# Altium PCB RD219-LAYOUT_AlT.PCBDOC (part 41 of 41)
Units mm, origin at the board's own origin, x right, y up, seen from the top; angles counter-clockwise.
Board outline 209.75 x 159.97 mm, 2 copper layers (TOP, BOTTOM), stack 0 mm thick; 398 components, 199 nets, 1469 pads, 0 vias.
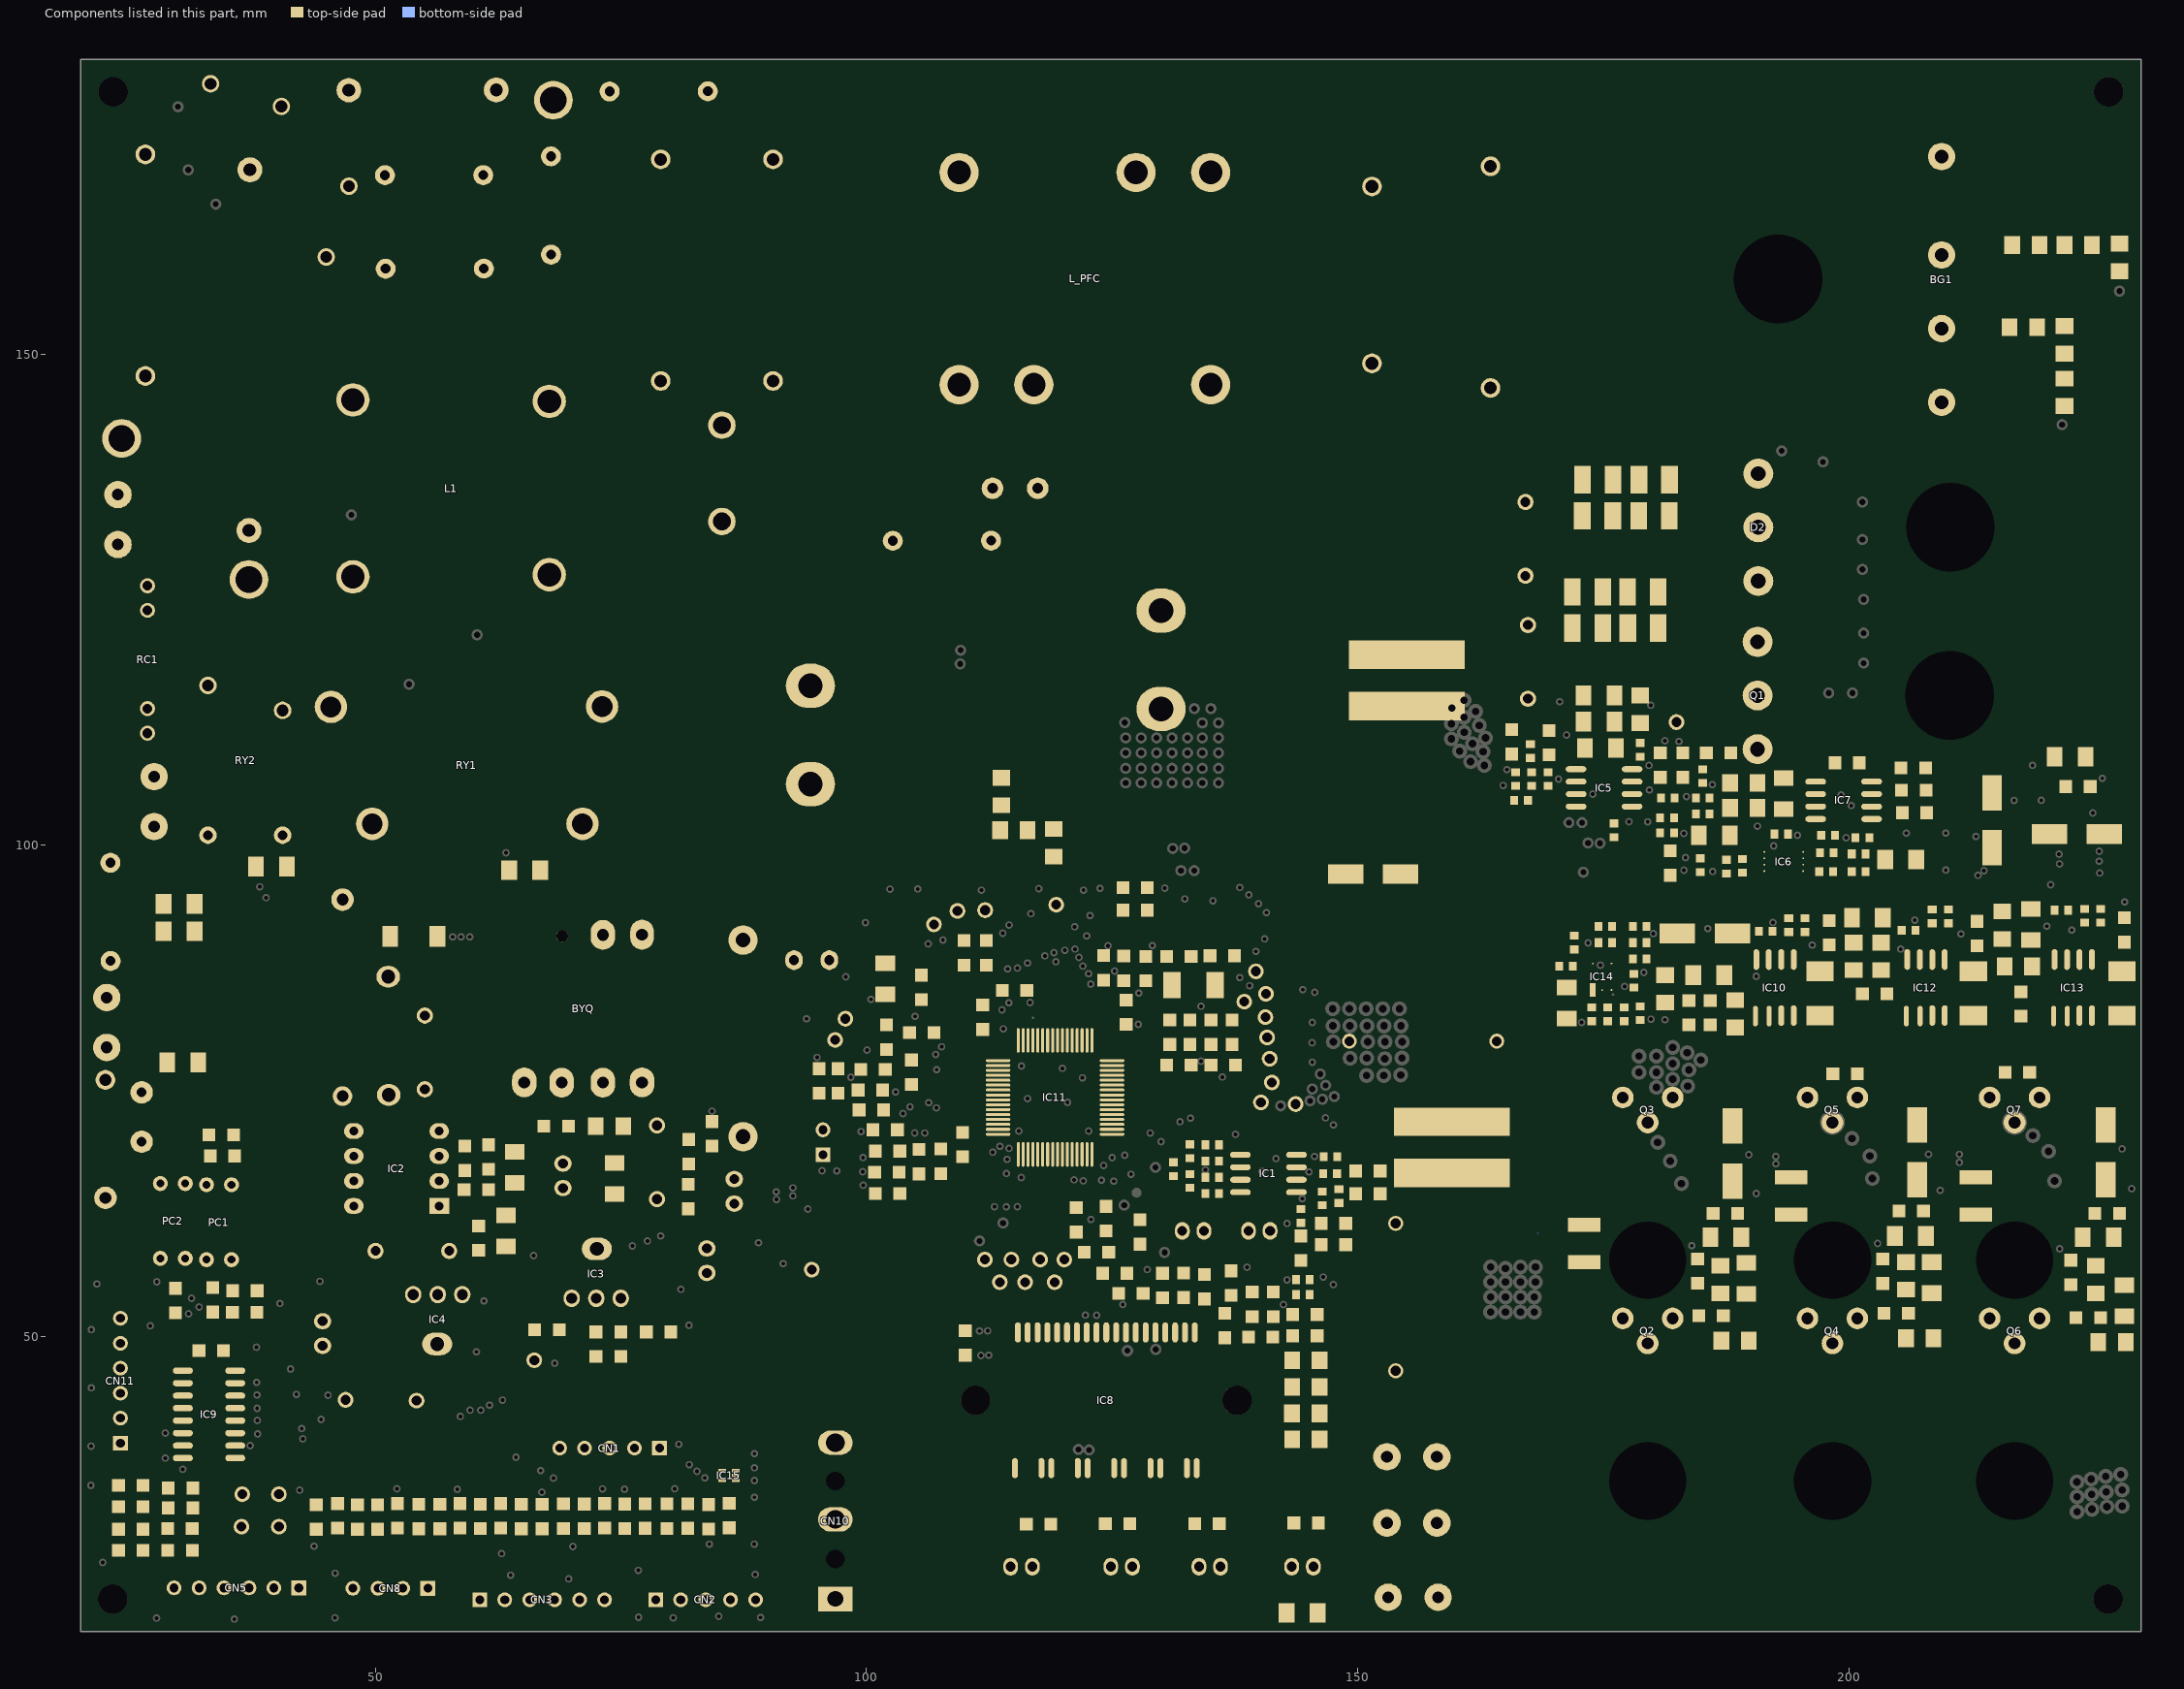
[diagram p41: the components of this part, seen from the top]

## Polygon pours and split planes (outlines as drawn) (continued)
no net on Bottom Solder "BOTTOMSOLDER377" (solid, pour order 0): 187.178,122.13 187.178,123.378 189.372,123.378 189.372,122.13
no net on Bottom Solder "BOTTOMSOLDER376" (solid, pour order 0): 184.638,122.13 184.638,123.378 186.832,123.378 186.832,122.13
no net on Bottom Solder "BOTTOMSOLDER375" (solid, pour order 0): 153.033,116.838 151.636,118.235 155.192,121.791 156.589,120.394
no net on Bottom Solder "BOTTOMSOLDER374" (solid, pour order 0): 160.843,125.791 160.843,128.331 164.297,128.331 164.297,125.791
no net on Bottom Solder "BOTTOMSOLDER373" (solid, pour order 0): 150.937,84.77 150.937,87.987 153.477,87.987 153.477,84.77
no net on Bottom Solder "BOTTOMSOLDER372" (solid, pour order 0): 147.339,85.024 147.339,90.612 149.879,90.612 149.879,85.024
no net on Bottom Solder "BOTTOMSOLDER371" (solid, pour order 0): 145.913,90.828 142.357,94.384 143.754,95.781 147.31,92.225
no net on Bottom Solder "BOTTOMSOLDER370" (solid, pour order 0): 148.707,92.479 145.151,96.035 146.548,97.432 150.104,93.876
no net on Bottom Solder "BOTTOMSOLDER369" (solid, pour order 0): 142.191,94.731 138.635,98.287 140.032,99.684 143.588,96.128
no net on Bottom Solder "BOTTOMSOLDER368" (solid, pour order 0): 144.227,96.725 140.671,100.281 142.068,101.678 145.624,98.122
no net on Bottom Solder "BOTTOMSOLDER367" (solid, pour order 0): 137.747,99.33 134.191,102.886 135.588,104.283 139.144,100.727
no net on Bottom Solder "BOTTOMSOLDER366" (solid, pour order 0): 139.84,101.165 136.284,104.721 137.681,106.118 141.237,102.562
no net on Bottom Solder "BOTTOMSOLDER365" (solid, pour order 0): 116.87,102.511 116.87,105.051 125.283,105.051 125.283,102.511
no net on Bottom Solder "BOTTOMSOLDER364" (solid, pour order 0): 110.437,102.642 110.437,105.182 116.025,105.182 116.025,102.642
no net on Bottom Solder "BOTTOMSOLDER363" (solid, pour order 0): 104.016,102.883 104.016,105.423 109.604,105.423 109.604,102.883
no net on Bottom Solder "BOTTOMSOLDER362" (solid, pour order 0): 91.501,100.525 91.501,103.065 95.494,103.065 95.494,100.525
no net on Bottom Solder "BOTTOMSOLDER361" (solid, pour order 0): 161.11,91.133 158.4,93.843 159.797,95.24 162.507,92.53
no net on Bottom Solder "BOTTOMSOLDER360" (solid, pour order 0): 165.026,91.517 161.47,95.073 163.574,97.177 163.701,97.176 165.375,95.483 167.129,93.748 167.13,93.621
no net on Bottom Solder "BOTTOMSOLDER359" (solid, pour order 0): 157.595,94.859 154.039,98.415 155.436,99.812 158.992,96.256
no net on Bottom Solder "BOTTOMSOLDER358" (solid, pour order 0): 153.181,99.021 149.625,102.577 151.022,103.974 154.578,100.418
no net on Bottom Solder "BOTTOMSOLDER357" (solid, pour order 0): 160.824,95.668 157.268,99.224 159.371,101.327 159.498,101.327 161.173,99.633 162.927,97.898 162.927,97.771
no net on Bottom Solder "BOTTOMSOLDER356" (solid, pour order 0): 156.493,100.166 152.937,103.722 155.04,105.826 155.167,105.825 156.842,104.132 158.596,102.397 158.596,102.27
no net on Bottom Solder "BOTTOMSOLDER355" (solid, pour order 0): 148.976,103.436 145.42,106.992 146.817,108.389 150.373,104.833
no net on Bottom Solder "BOTTOMSOLDER354" (solid, pour order 0): 151.826,104.833 148.27,108.389 150.374,110.492 150.501,110.492 152.175,108.799 153.929,107.063 153.93,106.936
no net on Bottom Solder "BOTTOMSOLDER353" (solid, pour order 0): 149.733,111.684 149.733,117.272 152.273,117.272 152.273,111.684
no net on Bottom Solder "BOTTOMSOLDER352" (solid, pour order 0): 143.063,109.281 143.063,117.663 145.603,117.663 145.603,109.281
no net on Bottom Solder "BOTTOMSOLDER351" (solid, pour order 0): 145.603,118.298 145.603,120.838 151.191,120.838 151.191,118.298
no net on Bottom Solder "BOTTOMSOLDER350" (solid, pour order 0): 153.277,121.761 153.277,124.301 158.865,124.301 158.865,121.761
no net on Bottom Solder "BOTTOMSOLDER349" (solid, pour order 0): 153.984,125.156 153.984,127.696 159.572,127.696 159.572,125.156
no net on Bottom Solder "BOTTOMSOLDER348" (solid, pour order 0): 154.576,128.785 154.576,131.325 160.164,131.325 160.164,128.785
no net on Bottom Solder "BOTTOMSOLDER347" (solid, pour order 0): 124.386,125.107 124.386,130.695 126.926,130.695 126.926,125.107
no net on Bottom Solder "BOTTOMSOLDER346" (solid, pour order 0): 120.965,121.727 120.965,124.267 126.553,124.267 126.553,121.727
no net on Bottom Solder "BOTTOMSOLDER345" (solid, pour order 0): 117.917,118.933 117.917,121.473 123.505,121.473 123.505,118.933
no net on Bottom Solder "BOTTOMSOLDER344" (solid, pour order 0): 121.092,125.156 121.092,130.744 123.632,130.744 123.632,125.156
no net on Bottom Solder "BOTTOMSOLDER343" (solid, pour order 0): 117.79,122.362 117.79,127.95 120.33,127.95 120.33,122.362
no net on Bottom Solder "BOTTOMSOLDER342" (solid, pour order 0): 165.74,139.218 165.74,142.266 171.328,142.266 171.328,139.218
no net on Bottom Solder "BOTTOMSOLDER341" (solid, pour order 0): 135.043,138.647 131.487,142.203 133.59,144.306 133.717,144.306 135.392,142.613 137.146,140.877 137.146,140.75
no net on Bottom Solder "BOTTOMSOLDER340" (solid, pour order 0): 126.454,143.124 126.454,145.664 132.042,145.664 132.042,143.124
no net on Bottom Solder "BOTTOMSOLDER339" (solid, pour order 0): 120.33,143.063 120.33,145.603 125.918,145.603 125.918,143.063
no net on Bottom Solder "BOTTOMSOLDER338" (solid, pour order 0): 100.772,140.777 100.772,146.365 103.312,146.365 103.312,140.777
no net on Bottom Solder "BOTTOMSOLDER337" (solid, pour order 0): 98.3,135.254 96.903,136.651 100.459,140.207 101.856,138.81
no net on Bottom Solder "BOTTOMSOLDER336" (solid, pour order 0): 93.74,130.995 92.343,132.392 95.899,135.948 97.296,134.551
no net on Bottom Solder "BOTTOMSOLDER335" (solid, pour order 0): 96.063,137.529 93.96,139.633 97.516,143.189 99.619,141.085 99.619,140.958 97.926,139.284 96.19,137.53
no net on Bottom Solder "BOTTOMSOLDER334" (solid, pour order 0): 91.515,133.077 89.412,135.18 92.968,138.736 95.071,136.633 95.071,136.506 93.378,134.832 91.642,133.077
no net on Bottom Solder "BOTTOMSOLDER333" (solid, pour order 0): 89.505,127.141 87.401,129.244 90.957,132.8 93.061,130.697 93.06,130.57 91.367,128.895 89.632,127.141
no net on Bottom Solder "BOTTOMSOLDER332" (solid, pour order 0): 80.313,124.699 78.209,126.802 81.765,130.358 83.869,128.255 83.868,128.128 82.175,126.454 80.44,124.699
no net on Bottom Solder "BOTTOMSOLDER331" (solid, pour order 0): 84.143,122.401 82.039,124.504 85.595,128.06 87.699,125.957 87.698,125.83 86.005,124.156 84.27,122.401
no net on Bottom Solder "BOTTOMSOLDER330" (solid, pour order 0): 80.312,116.384 80.312,121.972 82.852,121.972 82.852,116.384
no net on Bottom Solder "BOTTOMSOLDER329" (solid, pour order 0): 21.067,146.017 21.067,150.83 23.607,150.83 23.607,146.017
no net on Bottom Solder "BOTTOMSOLDER328" (solid, pour order 0): 59.924,160.83 59.924,165.643 62.032,165.643 62.032,160.83
no net on Bottom Solder "BOTTOMSOLDER327" (solid, pour order 0): 63.231,169.385 63.231,174.198 65.771,174.198 65.771,169.385
no net on Bottom Solder "BOTTOMSOLDER326" (solid, pour order 0): 60.437,170.401 60.437,175.214 62.977,175.214 62.977,170.401
no net on Bottom Solder "BOTTOMSOLDER325" (solid, pour order 0): 72.766,153 71.369,154.397 74.925,157.953 76.322,156.556
no net on Bottom Solder "BOTTOMSOLDER324" (solid, pour order 0): 68.444,148.566 67.047,149.963 70.603,153.519 72,152.122
no net on Bottom Solder "BOTTOMSOLDER323" (solid, pour order 0): 43.341,148.253 43.341,150.793 48.929,150.793 48.929,148.253
no net on Bottom Solder "BOTTOMSOLDER322" (solid, pour order 0): 44.384,155.001 44.384,157.541 49.972,157.541 49.972,155.001
no net on Bottom Solder "BOTTOMSOLDER321" (solid, pour order 0): 79.262,136.611 77.159,138.714 80.715,142.27 82.818,140.167 82.817,140.04 81.124,138.365 79.389,136.611
no net on Bottom Solder "BOTTOMSOLDER320" (solid, pour order 0): 76.768,139.362 75.371,140.759 78.927,144.315 80.324,142.918
no net on Bottom Solder "BOTTOMSOLDER319" (solid, pour order 0): 74.999,132.551 72.895,134.654 76.451,138.21 78.555,136.107 78.554,135.98 76.861,134.305 75.126,132.551
no net on Bottom Solder "BOTTOMSOLDER318" (solid, pour order 0): 72.571,135.292 71.174,136.689 74.73,140.245 76.127,138.848
no net on Bottom Solder "BOTTOMSOLDER317" (solid, pour order 0): 67.959,130.953 66.562,132.35 70.118,135.906 71.515,134.509
no net on Bottom Solder "BOTTOMSOLDER316" (solid, pour order 0): 60.69,123.387 59.293,124.784 62.849,128.34 64.246,126.943
no net on Bottom Solder "BOTTOMSOLDER315" (solid, pour order 0): 56.484,113.564 54.373,115.675 59.511,120.813 61.614,118.71 61.613,118.583 59.92,116.908 56.611,113.564
no net on Bottom Solder "BOTTOMSOLDER314" (solid, pour order 0): 56.532,119.291 55.135,120.688 58.691,124.244 60.088,122.847
no net on Bottom Solder "BOTTOMSOLDER313" (solid, pour order 0): 51.434,110.675 51.434,116.263 53.974,116.263 53.974,110.675
no net on Bottom Solder "BOTTOMSOLDER312" (solid, pour order 0): 171.384,129.358 171.384,131.263 178.844,131.263 178.844,129.358
no net on Bottom Solder "BOTTOMSOLDER311" (solid, pour order 0): 161.859,128.839 161.859,131.379 170.114,131.379 170.114,128.839
no net on Bottom Solder "BOTTOMSOLDER310" (solid, pour order 0): 127.569,128.204 127.569,130.744 133.157,130.744 133.157,128.204
no net on Bottom Solder "BOTTOMSOLDER309" (solid, pour order 0): 96.2,118.679 96.2,124.267 98.74,124.267 98.74,118.679
no net on Bottom Solder "BOTTOMSOLDER308" (solid, pour order 0): 140.269,121.727 140.269,124.267 145.857,124.267 145.857,121.727
no net on Bottom Solder "BOTTOMSOLDER307" (solid, pour order 0): 146.238,111.44 146.238,117.028 148.778,117.028 148.778,111.44
no net on Bottom Solder "BOTTOMSOLDER306" (solid, pour order 0): 168.102,173.621 168.102,176.161 173.69,176.161 173.69,173.621
no net on Bottom Solder "BOTTOMSOLDER305" (solid, pour order 0): 174.478,176.572 174.478,179.112 180.066,179.112 180.066,176.572
no net on Bottom Solder "BOTTOMSOLDER304" (solid, pour order 0): 174.364,173.644 174.364,176.184 179.952,176.184 179.952,173.644
no net on Bottom Solder "BOTTOMSOLDER303" (solid, pour order 0): 180.732,173.644 180.732,176.184 186.32,176.184 186.32,173.644
no net on Bottom Solder "BOTTOMSOLDER302" (solid, pour order 0): 138.028,154.973 138.028,157.513 143.616,157.513 143.616,154.973
no net on Bottom Solder "BOTTOMSOLDER301" (solid, pour order 0): 145.309,154.973 145.309,157.513 150.897,157.513 150.897,154.973
no net on Bottom Solder "BOTTOMSOLDER300" (solid, pour order 0): 152.59,154.973 152.59,157.513 158.178,157.513 158.178,154.973
no net on Bottom Solder "BOTTOMSOLDER299" (solid, pour order 0): 159.871,154.973 159.871,157.513 165.459,157.513 165.459,154.973
no net on Bottom Solder "BOTTOMSOLDER298" (solid, pour order 0): 167.152,154.973 167.152,157.513 172.74,157.513 172.74,154.973
no net on Bottom Solder "BOTTOMSOLDER297" (solid, pour order 0): 174.433,154.973 174.433,157.513 180.021,157.513 180.021,154.973
no net on Bottom Solder "BOTTOMSOLDER296" (solid, pour order 0): 184.652,153.537 181.096,157.093 183.199,159.196 183.326,159.195 185,157.502 186.754,155.767 186.755,155.64
no net on Bottom Solder "BOTTOMSOLDER295" (solid, pour order 0): 98.337,173.482 98.337,176.022 103.925,176.022 103.925,173.482
no net on Bottom Solder "BOTTOMSOLDER294" (solid, pour order 0): 98.337,176.403 98.337,178.943 103.925,178.943 103.925,176.403
no net on Bottom Solder "BOTTOMSOLDER293" (solid, pour order 0): 92.241,176.403 92.241,178.943 97.829,178.943 97.829,176.403
no net on Bottom Solder "BOTTOMSOLDER292" (solid, pour order 0): 92.241,173.355 92.241,175.895 97.829,175.895 97.829,173.355
no net on Bottom Solder "BOTTOMSOLDER291" (solid, pour order 0): 86.04,173.289 86.04,175.829 91.628,175.829 91.628,173.289
no net on Bottom Solder "BOTTOMSOLDER290" (solid, pour order 0): 86.018,176.403 86.018,178.943 91.606,178.943 91.606,176.403
no net on Bottom Solder "BOTTOMSOLDER289" (solid, pour order 0): 86.433,170.916 86.433,173.025 91.246,173.025 91.246,170.916
no net on Bottom Solder "BOTTOMSOLDER288" (solid, pour order 0): 91.894,170.916 91.894,173.025 96.707,173.025 96.707,170.916
no net on Bottom Solder "BOTTOMSOLDER287" (solid, pour order 0): 130.747,154.973 130.747,157.513 136.335,157.513 136.335,154.973
no net on Bottom Solder "BOTTOMSOLDER286" (solid, pour order 0): 123.466,154.973 123.466,157.513 129.054,157.513 129.054,154.973
no net on Bottom Solder "BOTTOMSOLDER285" (solid, pour order 0): 116.185,154.973 116.185,157.513 121.773,157.513 121.773,154.973
no net on Bottom Solder "BOTTOMSOLDER284" (solid, pour order 0): 108.904,154.973 108.904,157.513 114.492,157.513 114.492,154.973
no net on Bottom Solder "BOTTOMSOLDER283" (solid, pour order 0): 130.38,158.228 130.38,160.768 135.968,160.768 135.968,158.228
no net on Bottom Solder "BOTTOMSOLDER282" (solid, pour order 0): 122.996,158.228 122.996,160.768 128.584,160.768 128.584,158.228
no net on Bottom Solder "BOTTOMSOLDER281" (solid, pour order 0): 115.612,158.228 115.612,160.768 121.2,160.768 121.2,158.228
no net on Bottom Solder "BOTTOMSOLDER280" (solid, pour order 0): 108.228,158.228 108.228,160.768 113.816,160.768 113.816,158.228
no net on Bottom Solder "BOTTOMSOLDER279" (solid, pour order 0): 104.355,154.86 104.355,160.448 106.895,160.448 106.895,154.86
no net on Bottom Solder "BOTTOMSOLDER278" (solid, pour order 0): 200.033,125.664 192.519,125.664 192.519,128.712 200.033,128.712
no net on Bottom Solder "BOTTOMSOLDER277" (solid, pour order 0): 193.187,113.579 193.187,114.827 195.38,114.827 195.38,113.579
no net on Bottom Solder "BOTTOMSOLDER276" (solid, pour order 0): 195.814,113.621 195.814,114.869 198.008,114.869 198.008,113.621
no net on Bottom Solder "BOTTOMSOLDER275" (solid, pour order 0): 198.481,113.621 198.481,114.869 200.675,114.869 200.675,113.621
no net on Bottom Solder "BOTTOMSOLDER274" (solid, pour order 0): 196.636,115.404 196.636,116.651 198.829,116.651 198.829,115.404
no net on Bottom Solder "BOTTOMSOLDER273" (solid, pour order 0): 193.572,115.619 193.572,116.867 195.765,116.867 195.765,115.619
no net on Bottom Solder "BOTTOMSOLDER272" (solid, pour order 0): 197.76,116.973 197.76,118.221 199.953,118.221 199.953,116.973
no net on Bottom Solder "BOTTOMSOLDER271" (solid, pour order 0): 200.086,115.377 200.086,120.965 203.769,120.965 203.769,115.377
no net on Bottom Solder "BOTTOMSOLDER270" (solid, pour order 0): 200.213,121.219 200.213,126.807 203.896,126.807 203.896,121.219
no net on Bottom Solder "BOTTOMSOLDER269" (solid, pour order 0): 200.785,127.823 200.785,133.411 204.468,133.411 204.468,127.823
no net on Bottom Solder "BOTTOMSOLDER268" (solid, pour order 0): 200.721,134.427 200.721,140.015 204.404,140.015 204.404,134.427
no net on Bottom Solder "BOTTOMSOLDER267" (solid, pour order 0): 199.219,137.013 199.219,139.207 200.467,139.207 200.467,137.013
no net on Bottom Solder "BOTTOMSOLDER266" (solid, pour order 0): 199.027,140.224 199.027,142.418 200.275,142.418 200.275,140.224
no net on Bottom Solder "BOTTOMSOLDER265" (solid, pour order 0): 201.286,140.191 201.286,142.384 202.533,142.384 202.533,140.191
no net on Bottom Solder "BOTTOMSOLDER264" (solid, pour order 0): 199.324,131.552 199.324,133.746 200.572,133.746 200.572,131.552
no net on Bottom Solder "BOTTOMSOLDER263" (solid, pour order 0): 160.081,54.036 160.081,58.862 162.367,58.862 162.367,54.036
no net on Bottom Solder "BOTTOMSOLDER262" (solid, pour order 0): 202.652,50.92 202.652,55.201 205.192,55.201 205.192,50.92
no net on Bottom Solder "BOTTOMSOLDER261" (solid, pour order 0): 183.83,50.834 183.83,55.116 186.37,55.116 186.37,50.834
no net on Bottom Solder "BOTTOMSOLDER260" (solid, pour order 0): 191.958,139.634 191.958,142.682 197.546,142.682 197.546,139.634
no net on Bottom Solder "BOTTOMSOLDER259" (solid, pour order 0): 185.166,139.69 185.166,142.738 190.754,142.738 190.754,139.69
no net on Bottom Solder "BOTTOMSOLDER258" (solid, pour order 0): 178.75,139.634 178.75,142.682 184.338,142.682 184.338,139.634
no net on Bottom Solder "BOTTOMSOLDER257" (solid, pour order 0): 172.4,139.634 172.4,142.682 177.988,142.682 177.988,139.634
no net on Bottom Solder "BOTTOMSOLDER256" (solid, pour order 0): 185.717,131.121 185.717,132.369 187.911,132.369 187.911,131.121
no net on Bottom Solder "BOTTOMSOLDER255" (solid, pour order 0): 197.909,69.018 197.909,70.266 200.103,70.266 200.103,69.018
no net on Bottom Solder "BOTTOMSOLDER254" (solid, pour order 0): 177.091,63.841 177.091,66.355 179.647,66.355 179.647,63.841
no net on Bottom Solder "BOTTOMSOLDER253" (solid, pour order 0): 191.178,75.241 191.178,76.489 193.372,76.489 193.372,75.241
no net on Bottom Solder "BOTTOMSOLDER252" (solid, pour order 0): 217.594,76.384 217.594,77.632 219.788,77.632 219.788,76.384
no net on Bottom Solder "BOTTOMSOLDER251" (solid, pour order 0): 217.594,78.289 217.594,79.537 219.788,79.537 219.788,78.289
no net on Bottom Solder "BOTTOMSOLDER250" (solid, pour order 0): 211.364,76.699 211.364,79.239 216.952,79.239 216.952,76.699
no net on Bottom Solder "BOTTOMSOLDER249" (solid, pour order 0): 204.633,74.159 204.633,76.699 210.221,76.699 210.221,74.159
no net on Bottom Solder "BOTTOMSOLDER248" (solid, pour order 0): 205.141,77.461 205.141,80.001 210.729,80.001 210.729,77.461
no net on Bottom Solder "BOTTOMSOLDER247" (solid, pour order 0): 198.816,76.642 198.816,79.182 204.404,79.182 204.404,76.642
no net on Bottom Solder "BOTTOMSOLDER246" (solid, pour order 0): 192.568,77.334 192.568,79.874 198.156,79.874 198.156,77.334
no net on Bottom Solder "BOTTOMSOLDER245" (solid, pour order 0): 185.075,73.905 185.075,76.445 190.663,76.445 190.663,73.905
no net on Bottom Solder "BOTTOMSOLDER244" (solid, pour order 0): 186.091,76.953 186.091,79.493 191.679,79.493 191.679,76.953
no net on Bottom Solder "BOTTOMSOLDER243" (solid, pour order 0): 186.41,62.126 183.187,65.349 184.97,67.132 185.097,67.131 186.771,65.438 188.191,64.033 188.191,63.906
no net on Bottom Solder "BOTTOMSOLDER242" (solid, pour order 0): 205.271,61.278 201.715,64.834 203.818,66.937 203.945,66.937 205.62,65.244 207.374,63.508 207.374,63.381
no net on Bottom Solder "BOTTOMSOLDER241" (solid, pour order 0): 205.628,56.661 205.628,61.614 208.168,61.614 208.168,56.661
no net on Bottom Solder "BOTTOMSOLDER240" (solid, pour order 0): 205.628,51.2 205.628,56.153 208.168,56.153 208.168,51.2
no net on Bottom Solder "BOTTOMSOLDER239" (solid, pour order 0): 205.501,45.612 205.501,50.565 208.041,50.565 208.041,45.612
no net on Bottom Solder "BOTTOMSOLDER238" (solid, pour order 0): 205.501,40.024 205.501,44.977 208.041,44.977 208.041,40.024
no net on Bottom Solder "BOTTOMSOLDER237" (solid, pour order 0): 205.501,34.309 205.501,39.262 208.041,39.262 208.041,34.309
no net on Bottom Solder "BOTTOMSOLDER236" (solid, pour order 0): 197.829,63.769 197.829,68.722 200.369,68.722 200.369,63.769
no net on Bottom Solder "BOTTOMSOLDER235" (solid, pour order 0): 180.401,63.625 180.401,68.578 182.941,68.578 182.941,63.625
no net on Bottom Solder "BOTTOMSOLDER234" (solid, pour order 0): 186.624,56.894 186.624,61.847 189.164,61.847 189.164,56.894
no net on Bottom Solder "BOTTOMSOLDER233" (solid, pour order 0): 186.624,51.687 186.624,56.64 189.164,56.64 189.164,51.687
no net on Bottom Solder "BOTTOMSOLDER232" (solid, pour order 0): 186.624,46.289 186.624,51.242 189.164,51.242 189.164,46.289
no net on Bottom Solder "BOTTOMSOLDER231" (solid, pour order 0): 186.1,40.414 183.814,42.7 187.37,46.256 189.656,43.97
no net on Bottom Solder "BOTTOMSOLDER230" (solid, pour order 0): 159.827,28.255 159.827,30.795 165.415,30.795 165.415,28.255
no net on Bottom Solder "BOTTOMSOLDER229" (solid, pour order 0): 159.827,31.176 159.827,33.716 165.415,33.716 165.415,31.176
no net on Bottom Solder "BOTTOMSOLDER228" (solid, pour order 0): 178.059,40.506 178.059,43.046 183.647,43.046 183.647,40.506
no net on Bottom Solder "BOTTOMSOLDER227" (solid, pour order 0): 171.973,40.536 171.973,43.076 177.561,43.076 177.561,40.536
no net on Bottom Solder "BOTTOMSOLDER226" (solid, pour order 0): 165.877,40.536 165.877,43.076 171.465,43.076 171.465,40.536
no net on Bottom Solder "BOTTOMSOLDER225" (solid, pour order 0): 159.781,40.536 159.781,43.076 165.369,43.076 165.369,40.536
no net on Bottom Solder "BOTTOMSOLDER224" (solid, pour order 0): 185.654,132.903 185.654,134.151 187.848,134.151 187.848,132.903
no net on Bottom Solder "BOTTOMSOLDER223" (solid, pour order 0): 166.405,77.446 166.405,79.639 167.652,79.639 167.652,77.446
no net on Bottom Solder "BOTTOMSOLDER222" (solid, pour order 0): 48.088,158.254 48.088,160.448 49.336,160.448 49.336,158.254
no net on Bottom Solder "BOTTOMSOLDER221" (solid, pour order 0): 27.894,166.539 27.894,168.733 29.141,168.733 29.141,166.539
no net on Bottom Solder "BOTTOMSOLDER220" (solid, pour order 0): 178.493,125.83 177.096,127.227 180.652,130.783 182.049,129.386
no net on Bottom Solder "BOTTOMSOLDER219" (solid, pour order 0): 179.221,131.284 179.221,133.824 184.809,133.824 184.809,131.284
no net on Bottom Solder "BOTTOMSOLDER218" (solid, pour order 0): 138.745,118.298 138.745,120.838 144.333,120.838 144.333,118.298
no net on Bottom Solder "BOTTOMSOLDER217" (solid, pour order 0): 54.798,59.497 54.798,62.037 56.195,62.037 56.195,60.005 55.687,59.497
no net on Bottom Solder "BOTTOMSOLDER216" (solid, pour order 0): 71.068,145.757 68.965,147.86 73.357,152.253 75.465,150.145 75.465,150.018 72.93,147.511 71.195,145.757
no net on Bottom Solder "BOTTOMSOLDER215" (solid, pour order 0): 62.432,119.404 60.329,121.508 64.722,125.901 66.829,123.793 66.829,123.666 64.294,121.159 62.559,119.405
no net on Bottom Solder "BOTTOMSOLDER214" (solid, pour order 0): 70.675,128.097 68.572,130.2 72.128,133.756 74.231,131.653 74.231,131.526 72.538,129.851 70.802,128.097
no net on Bottom Solder "BOTTOMSOLDER213" (solid, pour order 0): 147.242,78.99 147.242,84.578 149.782,84.578 149.782,78.99
no net on Bottom Solder "BOTTOMSOLDER212" (solid, pour order 0): 150.01,78.956 150.01,84.544 152.55,84.544 152.55,78.956
no net on Bottom Solder "BOTTOMSOLDER211" (solid, pour order 0): 150.47,75.753 150.47,78.293 155.032,78.293 155.032,75.753
no net on Bottom Solder "BOTTOMSOLDER210" (solid, pour order 0): 162.908,79.817 162.908,84.742 165.448,84.742 165.448,79.817
no net on Bottom Solder "BOTTOMSOLDER209" (solid, pour order 0): 169.606,112.478 169.606,115.736 171.427,115.736 171.427,112.478
no net on Bottom Solder "BOTTOMSOLDER208" (solid, pour order 0): 170.198,110.495 170.198,111.743 172.019,111.743 172.019,110.495
no net on Bottom Solder "BOTTOMSOLDER207" (solid, pour order 0): 170.518,109.095 170.518,110.342 172.711,110.342 172.711,109.095
no net on Bottom Solder "BOTTOMSOLDER206" (solid, pour order 0): 170.557,107.676 170.557,108.923 172.75,108.923 172.75,107.676
no net on Bottom Solder "BOTTOMSOLDER205" (solid, pour order 0): 174.242,107.821 172.845,109.218 176.401,112.774 177.798,111.377
no net on Bottom Solder "BOTTOMSOLDER204" (solid, pour order 0): 152.771,88.161 149.215,91.717 150.612,93.114 154.168,89.558
no net on Bottom Solder "BOTTOMSOLDER203" (solid, pour order 0): 153.031,78.928 153.031,84.516 154.939,84.516 154.939,78.928
no net on Bottom Solder "BOTTOMSOLDER202" (solid, pour order 0): 163.274,112.182 163.274,116.151 165.687,116.151 165.687,112.182
no net on Bottom Solder "BOTTOMSOLDER201" (solid, pour order 0): 135.65,97.31 134.267,98.693 135.005,99.432 136.389,98.048
no net on Bottom Solder "BOTTOMSOLDER200" (solid, pour order 0): 138.965,96.354 135.409,99.91 135.939,100.44 139.495,96.884
no net on Bottom Solder "BOTTOMSOLDER199" (solid, pour order 0): 27.139,171.463 27.139,173.495 32.727,173.495 32.727,171.463
no net on Bottom Solder "BOTTOMSOLDER198" (solid, pour order 0): 30.432,165.13 30.432,167.162 36.02,167.162 36.02,165.13
no net on Bottom Solder "BOTTOMSOLDER197" (solid, pour order 0): 186.35,119.059 186.35,120.307 188.543,120.307 188.543,119.059
no net on Bottom Solder "BOTTOMSOLDER196" (solid, pour order 0): 48.196,130.933 48.196,133.473 51.733,133.473 51.733,130.933
no net on Bottom Solder "BOTTOMSOLDER195" (solid, pour order 0): 43.895,130.884 43.895,133.424 47.432,133.424 47.432,130.884
no net on Bottom Solder "BOTTOMSOLDER194" (solid, pour order 0): 38.183,133.838 38.183,136.032 39.431,136.032 39.431,133.838
no net on Bottom Solder "BOTTOMSOLDER193" (solid, pour order 0): 38.437,128.758 38.437,130.952 39.685,130.952 39.685,128.758
no net on Bottom Solder "BOTTOMSOLDER192" (solid, pour order 0): 160.081,58.989 160.081,64.577 162.367,64.577 162.367,58.989
no net on Bottom Solder "BOTTOMSOLDER191" (solid, pour order 0): 41.717,175.829 41.717,177.861 45.845,177.861 45.845,175.829
no net on Bottom Solder "BOTTOMSOLDER190" (solid, pour order 0): 170.825,126.226 170.825,128.131 176.413,128.131 176.413,126.226
no net on Bottom Solder "BOTTOMSOLDER189" (solid, pour order 0): 177.049,66.87 177.049,69.383 179.606,69.383 179.606,66.87
no net on Bottom Solder "BOTTOMSOLDER188" (solid, pour order 0): 153.7,39.354 153.7,41.894 159.288,41.894 159.288,39.354
no net on Bottom Solder "BOTTOMSOLDER187" (solid, pour order 0): 120.41,145.9 120.41,148.44 125.998,148.44 125.998,145.9
no net on Bottom Solder "BOTTOMSOLDER186" (solid, pour order 0): 126.506,145.9 126.506,148.44 132.094,148.44 132.094,145.9
no net on Bottom Solder "BOTTOMSOLDER185" (solid, pour order 0): 216.454,63.474 216.454,66.014 219.759,66.014 219.759,63.474
no net on Bottom Solder "BOTTOMSOLDER184" (solid, pour order 0): 215.833,66.736 215.833,69.276 219.137,69.276 219.137,66.736
no net on Bottom Solder "BOTTOMSOLDER183" (solid, pour order 0): 222.692,37.082 222.692,42.035 225.232,42.035 225.232,37.082
no net on Bottom Solder "BOTTOMSOLDER182" (solid, pour order 0): 222.692,42.654 222.692,47.607 225.232,47.607 225.232,42.654
no net on Bottom Solder "BOTTOMSOLDER181" (solid, pour order 0): 222.692,48.226 222.692,53.179 225.232,53.179 225.232,48.226
no net on Bottom Solder "BOTTOMSOLDER180" (solid, pour order 0): 222.692,53.798 222.692,58.751 225.232,58.751 225.232,53.798
no net on Bottom Solder "BOTTOMSOLDER179" (solid, pour order 0): 222.692,59.37 222.692,64.323 225.232,64.323 225.232,59.37
no net on Bottom Solder "BOTTOMSOLDER178" (solid, pour order 0): 225.818,37.082 225.818,42.035 227.581,42.035 227.581,37.082
no net on Bottom Solder "BOTTOMSOLDER177" (solid, pour order 0): 225.818,42.615 225.818,47.568 227.581,47.568 227.581,42.615
no net on Bottom Solder "BOTTOMSOLDER176" (solid, pour order 0): 225.818,48.148 225.818,53.101 227.581,53.101 227.581,48.148
no net on Bottom Solder "BOTTOMSOLDER175" (solid, pour order 0): 225.818,53.682 225.818,58.635 227.581,58.635 227.581,53.682
no net on Bottom Solder "BOTTOMSOLDER174" (solid, pour order 0): 225.818,59.215 225.818,62.418 227.581,62.418 227.581,59.215
no net on Bottom Solder "BOTTOMSOLDER173" (solid, pour order 0): 221.954,64.724 221.954,65.971 224.147,65.971 224.147,64.724
no net on Bottom Solder "BOTTOMSOLDER172" (solid, pour order 0): 165.669,31.176 165.669,33.716 171.257,33.716 171.257,31.176
no net on Bottom Solder "BOTTOMSOLDER171" (solid, pour order 0): 171.592,27.939 171.592,30.479 177.18,30.479 177.18,27.939
no net on Bottom Solder "BOTTOMSOLDER170" (solid, pour order 0): 177.854,27.939 177.854,30.479 183.442,30.479 183.442,27.939
no net on Bottom Solder "BOTTOMSOLDER169" (solid, pour order 0): 184.117,27.939 184.117,30.479 189.705,30.479 189.705,27.939
no net on Bottom Solder "BOTTOMSOLDER168" (solid, pour order 0): 190.379,27.939 190.379,30.479 195.967,30.479 195.967,27.939
no net on Bottom Solder "BOTTOMSOLDER167" (solid, pour order 0): 196.642,27.939 196.642,30.479 202.23,30.479 202.23,27.939
no net on Bottom Solder "BOTTOMSOLDER166" (solid, pour order 0): 204.785,28.382 202.499,30.668 206.055,34.224 208.341,31.938
no net on Bottom Solder "BOTTOMSOLDER165" (solid, pour order 0): 171.638,25.031 171.638,27.128 177.226,27.128 177.226,25.031
no net on Bottom Solder "BOTTOMSOLDER164" (solid, pour order 0): 178.041,25.031 178.041,27.128 183.629,27.128 183.629,25.031
no net on Bottom Solder "BOTTOMSOLDER163" (solid, pour order 0): 184.444,25.031 184.444,27.128 190.032,27.128 190.032,25.031
no net on Bottom Solder "BOTTOMSOLDER162" (solid, pour order 0): 190.847,25.031 190.847,27.128 196.435,27.128 196.435,25.031
no net on Bottom Solder "BOTTOMSOLDER161" (solid, pour order 0): 197.25,25.031 197.25,27.128 202.838,27.128 202.838,25.031
no net on Bottom Solder "BOTTOMSOLDER160" (solid, pour order 0): 165.669,28.255 165.669,30.795 171.257,30.795 171.257,28.255
no net on Bottom Solder "BOTTOMSOLDER159" (solid, pour order 0): 172.119,31.289 172.119,32.537 174.312,32.537 174.312,31.289
no net on Bottom Solder "BOTTOMSOLDER158" (solid, pour order 0): 75.813,151.209 74.416,152.606 77.972,156.162 79.369,154.765
no net on Bottom Solder "BOTTOMSOLDER157" (solid, pour order 0): 97.1,150.437 97.1,156.025 99.64,156.025 99.64,150.437
no net on Bottom Solder "BOTTOMSOLDER156" (solid, pour order 0): 100.656,146.881 100.656,152.469 103.196,152.469 103.196,146.881
no net on Bottom Solder "BOTTOMSOLDER155" (solid, pour order 0): 181.428,148.263 177.872,151.819 179.269,153.216 182.825,149.66
no net on Bottom Solder "BOTTOMSOLDER154" (solid, pour order 0): 183.46,150.549 179.904,154.105 181.301,155.502 184.857,151.946
no net on Bottom Solder "BOTTOMSOLDER153" (solid, pour order 0): 190.466,172.244 186.91,175.8 189.013,177.904 189.14,177.903 190.815,176.21 192.569,174.475 192.569,174.348
no net on Bottom Solder "BOTTOMSOLDER152" (solid, pour order 0): 189.418,168.717 185.862,172.273 187.259,173.67 190.815,170.114
no net on Bottom Solder "BOTTOMSOLDER151" (solid, pour order 0): 193.736,164.653 190.18,168.209 191.577,169.606 195.133,166.05
no net on Bottom Solder "BOTTOMSOLDER150" (solid, pour order 0): 197.8,160.335 194.244,163.891 195.641,165.288 199.197,161.732
no net on Bottom Solder "BOTTOMSOLDER149" (solid, pour order 0): 195.038,167.799 191.482,171.355 193.585,173.459 193.712,173.458 195.387,171.765 197.141,170.03 197.141,169.903
no net on Bottom Solder "BOTTOMSOLDER148" (solid, pour order 0): 204.367,154.112 204.367,155.36 206.561,155.36 206.561,154.112
no net on Bottom Solder "BOTTOMSOLDER147" (solid, pour order 0): 207.728,172.7 207.728,174.894 208.976,174.894 208.976,172.7
no net on Bottom Solder "BOTTOMSOLDER146" (solid, pour order 0): 212.913,167.366 212.913,169.56 214.161,169.56 214.161,167.366
no net on Bottom Solder "BOTTOMSOLDER145" (solid, pour order 0): 213.57,172.7 213.57,174.894 214.818,174.894 214.818,172.7
no net on Bottom Solder "BOTTOMSOLDER144" (solid, pour order 0): 213.697,170.16 213.697,172.354 214.945,172.354 214.945,170.16
no net on Bottom Solder "BOTTOMSOLDER143" (solid, pour order 0): 211.919,170.16 211.919,172.354 213.167,172.354 213.167,170.16
no net on Bottom Solder "BOTTOMSOLDER142" (solid, pour order 0): 209.749,172.747 209.749,174.94 210.997,174.94 210.997,172.747
no net on Bottom Solder "BOTTOMSOLDER141" (solid, pour order 0): 211.781,172.747 211.781,174.94 213.029,174.94 213.029,172.747
no net on Bottom Solder "BOTTOMSOLDER140" (solid, pour order 0): 211.551,153.854 211.551,155.101 213.744,155.101 213.744,153.854
no net on Bottom Solder "BOTTOMSOLDER139" (solid, pour order 0): 212.093,150.469 212.093,151.716 214.286,151.716 214.286,150.469
no net on Bottom Solder "BOTTOMSOLDER138" (solid, pour order 0): 201.502,162.043 201.502,164.583 207.09,164.583 207.09,162.043
no net on Bottom Solder "BOTTOMSOLDER137" (solid, pour order 0): 208.481,162.275 208.481,164.468 209.729,164.468 209.729,162.275
no net on Bottom Solder "BOTTOMSOLDER136" (solid, pour order 0): 211.108,162.327 211.108,164.52 212.356,164.52 212.356,162.327
no net on Bottom Solder "BOTTOMSOLDER135" (solid, pour order 0): 212.382,158.504 212.382,160.697 213.63,160.697 213.63,158.504
no net on Bottom Solder "BOTTOMSOLDER134" (solid, pour order 0): 199.697,153.026 199.697,155.566 203.634,155.566 203.634,153.026
no net on Bottom Solder "BOTTOMSOLDER133" (solid, pour order 0): 200.916,150.085 200.916,152.625 206.504,152.625 206.504,150.085
no net on Bottom Solder "BOTTOMSOLDER132" (solid, pour order 0): 185.735,148.524 185.735,151.064 191.323,151.064 191.323,148.524
no net on Bottom Solder "BOTTOMSOLDER131" (solid, pour order 0): 193.228,148.524 193.228,151.064 198.816,151.064 198.816,148.524
no net on Bottom Solder "BOTTOMSOLDER130" (solid, pour order 0): 199.367,163.406 195.811,166.962 197.915,169.065 198.042,169.065 199.716,167.372 201.47,165.636 201.471,165.509
no net on Bottom Solder "BOTTOMSOLDER129" (solid, pour order 0): 200.208,158.371 200.208,160.911 205.796,160.911 205.796,158.371
no net on Bottom Solder "BOTTOMSOLDER128" (solid, pour order 0): 213.199,161.579 213.199,163.773 214.446,163.773 214.446,161.579
no net on Bottom Solder "BOTTOMSOLDER127" (solid, pour order 0): 104.709,176.464 104.709,179.004 110.297,179.004 110.297,176.464
no net on Bottom Solder "BOTTOMSOLDER126" (solid, pour order 0): 110.932,176.464 110.932,179.004 116.52,179.004 116.52,176.464
no net on Bottom Solder "BOTTOMSOLDER125" (solid, pour order 0): 117.286,176.486 117.286,179.026 122.874,179.026 122.874,176.486
no net on Bottom Solder "BOTTOMSOLDER124" (solid, pour order 0): 123.505,176.464 123.505,179.004 129.093,179.004 129.093,176.464
no net on Bottom Solder "BOTTOMSOLDER123" (solid, pour order 0): 129.855,176.464 129.855,179.004 135.443,179.004 135.443,176.464
no net on Bottom Solder "BOTTOMSOLDER122" (solid, pour order 0): 142.047,176.464 142.047,179.004 147.635,179.004 147.635,176.464
no net on Bottom Solder "BOTTOMSOLDER121" (solid, pour order 0): 148.27,176.464 148.27,179.004 153.858,179.004 153.858,176.464
no net on Bottom Solder "BOTTOMSOLDER120" (solid, pour order 0): 154.874,176.464 154.874,179.004 160.462,179.004 160.462,176.464
no net on Bottom Solder "BOTTOMSOLDER119" (solid, pour order 0): 161.478,176.464 161.478,179.004 167.066,179.004 167.066,176.464
no net on Bottom Solder "BOTTOMSOLDER118" (solid, pour order 0): 168.082,176.464 168.082,179.004 173.67,179.004 173.67,176.464
no net on Bottom Solder "BOTTOMSOLDER117" (solid, pour order 0): 180.782,176.591 180.782,179.131 186.37,179.131 186.37,176.591
no net on Bottom Solder "BOTTOMSOLDER116" (solid, pour order 0): 137.765,158.228 137.765,160.768 143.353,160.768 143.353,158.228
no net on Bottom Solder "BOTTOMSOLDER115" (solid, pour order 0): 145.149,158.228 145.149,160.768 150.737,160.768 150.737,158.228
no net on Bottom Solder "BOTTOMSOLDER114" (solid, pour order 0): 152.533,158.228 152.533,160.768 158.121,160.768 158.121,158.228
no net on Bottom Solder "BOTTOMSOLDER113" (solid, pour order 0): 159.917,158.228 159.917,160.768 165.505,160.768 165.505,158.228
no net on Bottom Solder "BOTTOMSOLDER112" (solid, pour order 0): 167.302,158.228 167.302,160.768 172.89,160.768 172.89,158.228
no net on Bottom Solder "BOTTOMSOLDER111" (solid, pour order 0): 174.686,158.228 174.686,160.768 180.274,160.768 180.274,158.228
no net on Bottom Solder "BOTTOMSOLDER110" (solid, pour order 0): 74.483,158.303 74.483,160.843 80.071,160.843 80.071,158.303
no net on Bottom Solder "BOTTOMSOLDER109" (solid, pour order 0): 80.579,157.541 80.579,163.129 83.119,163.129 83.119,157.541
no net on Bottom Solder "BOTTOMSOLDER108" (solid, pour order 0): 83.627,165.288 83.627,170.876 86.167,170.876 86.167,165.288
no net on Bottom Solder "BOTTOMSOLDER107" (solid, pour order 0): 74.562,161.467 74.562,164.007 80.15,164.007 80.15,161.467
no net on Bottom Solder "BOTTOMSOLDER106" (solid, pour order 0): 72.639,152.873 71.242,154.27 74.798,157.826 76.195,156.429
no net on Bottom Solder "BOTTOMSOLDER105" (solid, pour order 0): 74.61,164.526 74.61,167.066 80.198,167.066 80.198,164.526
no net on Bottom Solder "BOTTOMSOLDER104" (solid, pour order 0): 80.579,163.637 80.579,169.225 83.119,169.225 83.119,163.637
no net on Bottom Solder "BOTTOMSOLDER103" (solid, pour order 0): 83.637,160.081 83.637,164.894 86.177,164.894 86.177,160.081
no net on Bottom Solder "BOTTOMSOLDER102" (solid, pour order 0): 86.599,163.289 86.599,168.102 89.139,168.102 89.139,163.289
no net on Bottom Solder "BOTTOMSOLDER101" (solid, pour order 0): 100.612,153.064 100.612,158.652 103.152,158.652 103.152,153.064
no net on Bottom Solder "BOTTOMSOLDER100" (solid, pour order 0): 104.709,173.543 104.709,176.083 110.297,176.083 110.297,173.543
no net on Bottom Solder "BOTTOMSOLDER99" (solid, pour order 0): 111.084,173.588 111.084,176.128 116.672,176.128 116.672,173.588
no net on Bottom Solder "BOTTOMSOLDER98" (solid, pour order 0): 117.282,173.67 117.282,176.21 122.87,176.21 122.87,173.67
no net on Bottom Solder "BOTTOMSOLDER97" (solid, pour order 0): 123.513,173.642 123.513,176.182 129.101,176.182 129.101,173.642
no net on Bottom Solder "BOTTOMSOLDER96" (solid, pour order 0): 129.883,173.686 129.883,176.226 135.471,176.226 135.471,173.686
no net on Bottom Solder "BOTTOMSOLDER95" (solid, pour order 0): 135.973,176.478 135.973,179.018 141.561,179.018 141.561,176.478
no net on Bottom Solder "BOTTOMSOLDER94" (solid, pour order 0): 135.896,173.644 135.896,176.184 141.484,176.184 141.484,173.644
no net on Bottom Solder "BOTTOMSOLDER93" (solid, pour order 0): 142.023,173.648 142.023,176.188 147.611,176.188 147.611,173.648
no net on Bottom Solder "BOTTOMSOLDER92" (solid, pour order 0): 148.302,173.672 148.302,176.212 153.89,176.212 153.89,173.672
no net on Bottom Solder "BOTTOMSOLDER91" (solid, pour order 0): 154.841,173.681 154.841,176.221 160.429,176.221 160.429,173.681
no net on Bottom Solder "BOTTOMSOLDER90" (solid, pour order 0): 161.551,173.606 161.551,176.146 167.139,176.146 167.139,173.606
no net on Bottom Solder "BOTTOMSOLDER89" (solid, pour order 0): 43.955,116.811 43.955,119.351 49.543,119.351 49.543,116.811
no net on Bottom Solder "BOTTOMSOLDER88" (solid, pour order 0): 50.12,116.809 50.12,119.349 55.052,119.349 55.052,116.809
no net on Bottom Solder "BOTTOMSOLDER87" (solid, pour order 0): 48.448,110.678 48.448,116.266 50.988,116.266 50.988,110.678
no net on Bottom Solder "BOTTOMSOLDER86" (solid, pour order 0): 88.707,102.55 88.707,108.138 91.247,108.138 91.247,102.55
no net on Bottom Solder "BOTTOMSOLDER85" (solid, pour order 0): 97.216,102.804 97.216,105.344 102.804,105.344 102.804,102.804
no net on Bottom Solder "BOTTOMSOLDER84" (solid, pour order 0): 97.343,106.106 97.343,108.646 102.931,108.646 102.931,106.106
no net on Bottom Solder "BOTTOMSOLDER83" (solid, pour order 0): 104.074,106.106 104.074,108.646 109.662,108.646 109.662,106.106
no net on Bottom Solder "BOTTOMSOLDER82" (solid, pour order 0): 104.201,109.027 104.201,111.567 109.789,111.567 109.789,109.027
no net on Bottom Solder "BOTTOMSOLDER81" (solid, pour order 0): 110.424,106.106 110.424,108.646 116.012,108.646 116.012,106.106
no net on Bottom Solder "BOTTOMSOLDER80" (solid, pour order 0): 110.424,109.281 110.424,111.821 116.012,111.821 116.012,109.281
no net on Bottom Solder "BOTTOMSOLDER79" (solid, pour order 0): 116.774,105.852 116.774,108.392 125.156,108.392 125.156,105.852
no net on Bottom Solder "BOTTOMSOLDER78" (solid, pour order 0): 116.901,109.281 116.901,111.821 125.156,111.821 125.156,109.281
no net on Bottom Solder "BOTTOMSOLDER77" (solid, pour order 0): 76.802,112.799 76.802,115.339 82.39,115.339 82.39,112.799
no net on Bottom Solder "BOTTOMSOLDER76" (solid, pour order 0): 73.302,116.36 73.302,121.948 75.842,121.948 75.842,116.36
no net on Bottom Solder "BOTTOMSOLDER75" (solid, pour order 0): 76.769,116.393 76.769,121.981 79.309,121.981 79.309,116.393
no net on Bottom Solder "BOTTOMSOLDER74" (solid, pour order 0): 97.089,143.952 97.089,149.54 99.629,149.54 99.629,143.952
no net on Bottom Solder "BOTTOMSOLDER73" (solid, pour order 0): 99.375,118.679 99.375,124.267 101.915,124.267 101.915,118.679
no net on Bottom Solder "BOTTOMSOLDER72" (solid, pour order 0): 102.677,118.679 102.677,124.267 105.217,124.267 105.217,118.679
no net on Bottom Solder "BOTTOMSOLDER71" (solid, pour order 0): 105.725,118.679 105.725,124.267 108.265,124.267 108.265,118.679
no net on Bottom Solder "BOTTOMSOLDER70" (solid, pour order 0): 108.9,118.679 108.9,124.267 111.44,124.267 111.44,118.679
no net on Bottom Solder "BOTTOMSOLDER69" (solid, pour order 0): 112.075,118.679 112.075,124.267 114.615,124.267 114.615,118.679
no net on Bottom Solder "BOTTOMSOLDER68" (solid, pour order 0): 114.996,118.679 114.996,124.267 117.536,124.267 117.536,118.679
no net on Bottom Solder "BOTTOMSOLDER67" (solid, pour order 0): 147.127,121.6 147.127,124.14 152.715,124.14 152.715,121.6
no net on Bottom Solder "BOTTOMSOLDER66" (solid, pour order 0): 147.127,125.283 147.127,127.823 152.715,127.823 152.715,125.283
no net on Bottom Solder "BOTTOMSOLDER65" (solid, pour order 0): 133.538,121.6 133.538,124.14 139.126,124.14 139.126,121.6
no net on Bottom Solder "BOTTOMSOLDER64" (solid, pour order 0): 139.761,125.41 139.761,127.95 145.349,127.95 145.349,125.41
no net on Bottom Solder "BOTTOMSOLDER63" (solid, pour order 0): 132.776,125.283 132.776,127.823 138.364,127.823 138.364,125.283
no net on Bottom Solder "BOTTOMSOLDER62" (solid, pour order 0): 147.762,128.585 147.762,131.125 153.35,131.125 153.35,128.585
no net on Bottom Solder "BOTTOMSOLDER61" (solid, pour order 0): 140.934,128.523 140.934,131.063 146.522,131.063 146.522,128.523
no net on Bottom Solder "BOTTOMSOLDER60" (solid, pour order 0): 134.173,128.458 134.173,130.998 139.761,130.998 139.761,128.458
no net on Bottom Solder "BOTTOMSOLDER59" (solid, pour order 0): 158.684,139.253 158.684,142.301 164.272,142.301 164.272,139.253
no net on Bottom Solder "BOTTOMSOLDER58" (solid, pour order 0): 151.572,139.253 151.572,142.301 157.16,142.301 157.16,139.253
no net on Bottom Solder "BOTTOMSOLDER57" (solid, pour order 0): 144.841,139.253 144.841,142.323 150.429,142.323 150.429,139.253
no net on Bottom Solder "BOTTOMSOLDER56" (solid, pour order 0): 137.602,139.253 137.602,141.793 143.19,141.793 143.19,139.253
no net on Bottom Solder "BOTTOMSOLDER55" (solid, pour order 0): 137.324,142.858 137.324,145.398 142.912,145.398 142.912,142.858
no net on Bottom Solder "BOTTOMSOLDER54" (solid, pour order 0): 28.739,140.083 28.739,145.671 31.279,145.671 31.279,140.083
no net on Bottom Solder "BOTTOMSOLDER53" (solid, pour order 0): 36.256,147.635 36.256,150.175 41.844,150.175 41.844,147.635
no net on Bottom Solder "BOTTOMSOLDER52" (solid, pour order 0): 29.403,147.602 29.403,150.142 34.991,150.142 34.991,147.602
no net on Bottom Solder "BOTTOMSOLDER51" (solid, pour order 0): 44.003,151.445 44.003,153.985 49.591,153.985 49.591,151.445
no net on Bottom Solder "BOTTOMSOLDER50" (solid, pour order 0): 37.145,151.191 37.145,153.731 42.733,153.731 42.733,151.191
no net on Bottom Solder "BOTTOMSOLDER49" (solid, pour order 0): 30.668,151.191 30.668,153.731 36.256,153.731 36.256,151.191
no net on Bottom Solder "BOTTOMSOLDER48" (solid, pour order 0): 23.683,151.191 23.683,153.731 29.271,153.731 29.271,151.191

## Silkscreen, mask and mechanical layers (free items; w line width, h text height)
Top Overlay:
  drawing of 13140 lines, arcs and shapes, not listed
  text "VAC AD" at 106.343,94.482 h0.8
  text "VDC AD" at 113.076,93.714 h0.8
  text "IAC AD" at 101.173,90.919 h0.8
  text "PFC FO" at 116.024,90.598 h0.8
  text "PFC PWM" at 140.654,87.49 h0.8
  text "EMG1" at 146.21,85.083 h0.8
  text "WL1" at 141.643,84.493 h0.8
  text "WH1" at 141.897,81.636 h0.8
  text "GND" at 94.603,81.489 h0.61
  text "VL1" at 141.999,79.286 h0.8
  text "VH1" at 142.215,77.025 h0.8
  text "UL1" at 142.38,74.651 h0.8
  text "UH1" at 139.04,70.815 h0.8
  text "GND" at 142.862,70.574 h0.8
  text "M4KL/M4ML" at 114.567,64.795 h0.8
  text "TEMP3" at 93.335,63.286 h0.8
  text "VH0" at 111.813,58.672 h0.8
  text "WH0" at 114.62,58.664 h0.8
  text "EMG0" at 117.154,58.672 h0.8
  text "UH0" at 108.578,55.044 h0.8
  text "+15V" at 93.354,53.328 h0.8
  text "WL0" at 118.967,52.176 h0.8
  text "UL0" at 112.166,52.152 h0.8
  text "VL0" at 115.622,52.152 h0.8
  text "EEV" at 26.937,46.038 h0.8 r270
  text "+12V" at 64.81,44.229 h0.8
  text "+5V" at 48.428,42.33 h0.8
  text "GND" at 55.524,41.387 h0.8
  text "SWD" at 72.32,41.305 h0.8
  text "LED4" at 37.013,34.8 h0.8
  text "LED3" at 40.951,34.8 h0.8
  text "LED1" at 35.204,28.448 h0.8
  text "LED2" at 38.921,28.444 h0.8
  text "UART" at 68.682,27.216 h0.8
  text "TEMP2" at 49.581,27.203 h0.8
  text "TEMP1" at 36.919,27.153 h0.8
Bottom Overlay:
  drawing of 594 lines, arcs and shapes, not listed
Top Solder:
  lines w0.15: 162.136,111.59 162.403,111.59 162.269,111.59 162.269,112.39 162.136,112.256
Bottom Solder:
  drawing of 540 lines, arcs and shapes, not listed
Mechanical 3:
  drawing of 951 lines, arcs and shapes, not listed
